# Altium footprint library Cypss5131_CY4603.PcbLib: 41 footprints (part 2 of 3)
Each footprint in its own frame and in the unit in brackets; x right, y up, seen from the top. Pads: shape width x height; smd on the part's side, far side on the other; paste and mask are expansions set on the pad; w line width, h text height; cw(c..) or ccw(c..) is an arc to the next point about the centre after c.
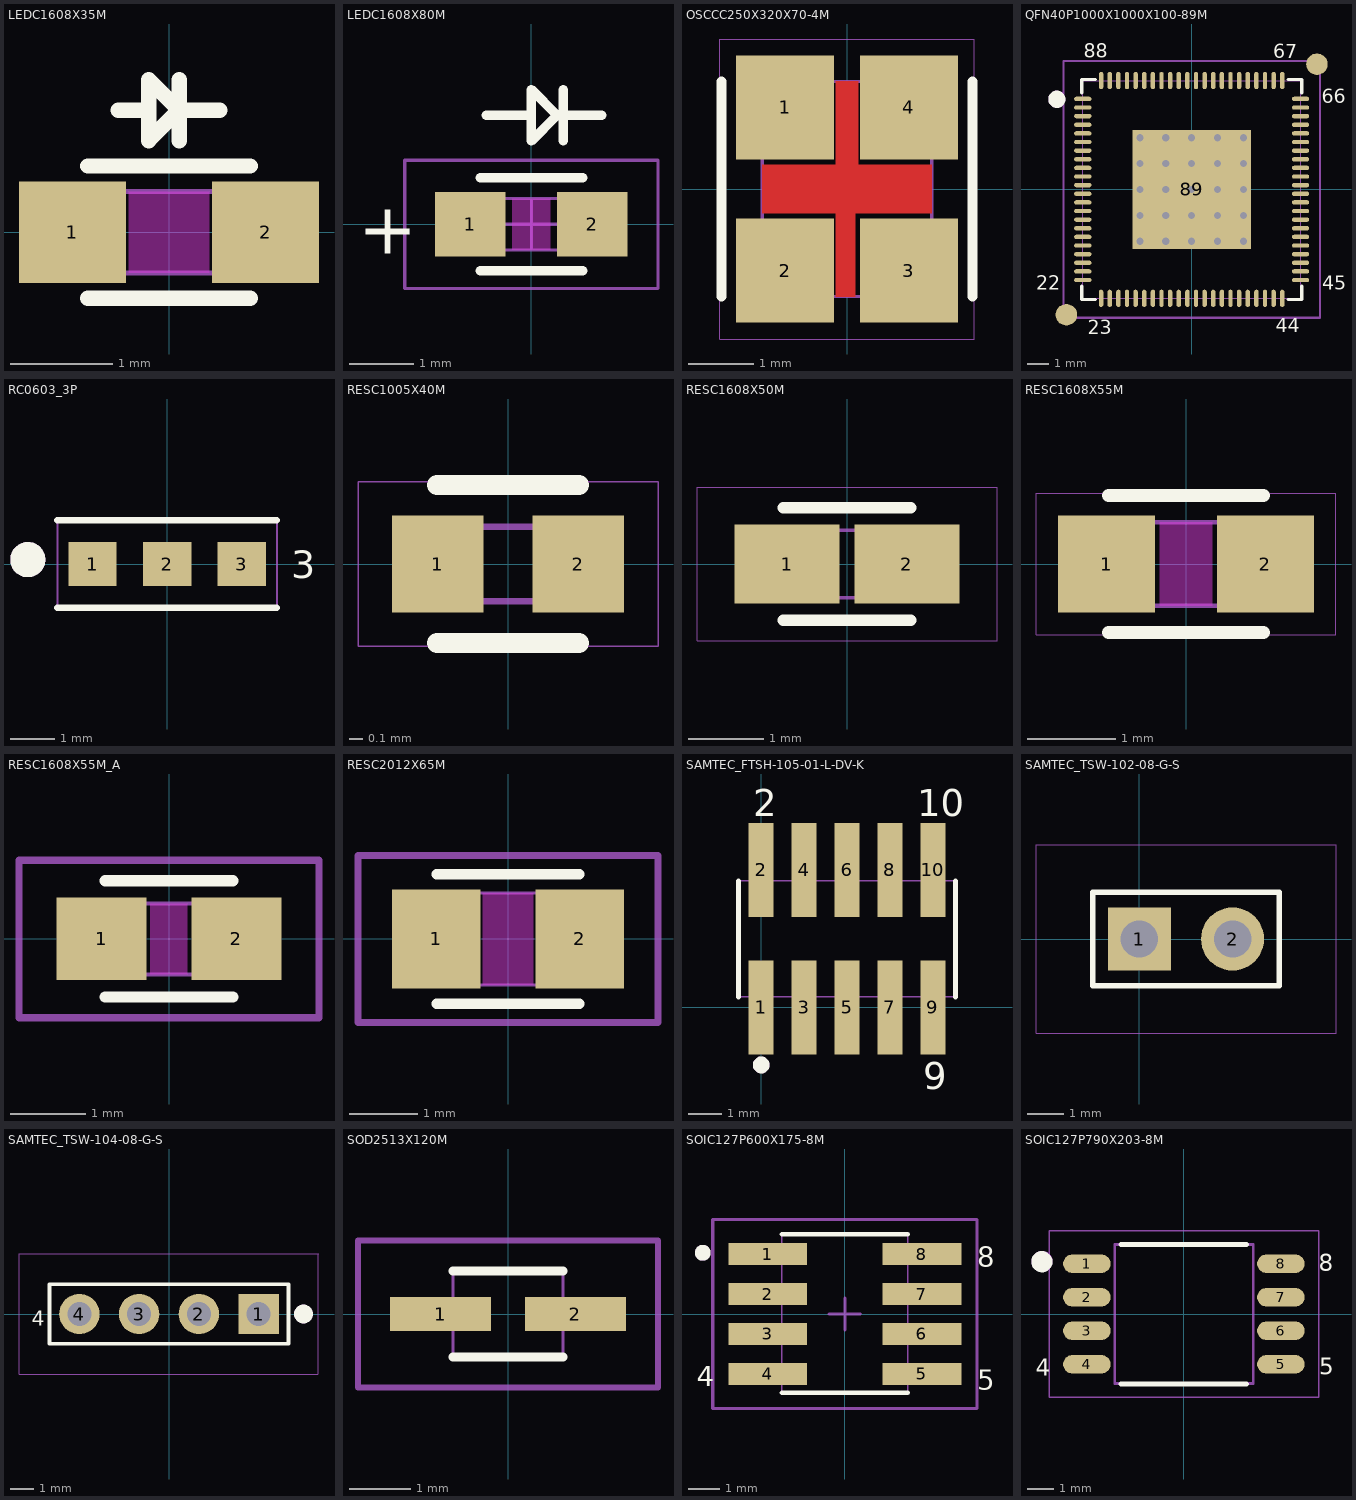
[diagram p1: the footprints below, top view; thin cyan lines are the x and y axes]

## LEDC1608X35M [mm]
height 0.35
pads (2):
  rect 1.05x1 smd mask+0: 1(-0.95,0) 2(0.95,0)
Top Layer keep-out:
  rectangle: -0.4,-0.4 0.4,0.4
Top Overlay:
  lines w0.15: -0.8,-0.65 0.8,-0.65 ; -0.8,0.65 0.8,0.65 ; -0.5,1.2 -0.2,1.2 ; 0.1,0.9 0.1,1.5 ; 0.5,1.2 0.1,1.2 ; 0.1,1.2 -0.2,0.9 -0.2,1.5 0.1,1.2
Mechanical 13:
  lines w0.05: -0.5,1.2 -0.2,1.2 ; 0.1,0.9 0.1,1.5 ; 0.5,1.2 0.1,1.2 ; 0.55,-0.4 0.55,0.4 ; 0.1,1.2 -0.2,0.9 -0.2,1.5 0.1,1.2 ; -0.8,-0.4 -0.8,0.4 0.8,0.4 0.8,-0.4 -0.8,-0.4
Mechanical 14:
  text "R105_100" at -2.4,-1.8 h0.64
  text "LEDC1608X35M" at -3.5,1.9 h0.64
3D body: height 0.35, standoff 0, extent -0.799,-0.4 0.8,0.4

## LEDC1608X80M [mm]
height 0.8
pads (2):
  rect 1.1x1 smd mask+0: 1(-0.95,0) 2(0.95,0)
Top Layer keep-out:
  rectangle: -0.3,-0.4 0.3,0.4
Top Overlay:
  lines w0.15: -0.8,-0.725 0.8,-0.725 ; -0.8,0.725 0.8,0.725 ; -0.7,1.7 0,1.7 ; 0.5,1.3 0.5,2.1 ; 1.1,1.7 0.4,1.7 ; 0,2.1 0,2.1 ; 0,2.1 0.4,1.7 ; 0,2.1 0,1.3 0.4,1.7
  text "+" at -2.705,-0.463 h0.8
  text ".Designator" at -3.7,3.9 h0.8
Mechanical 13:
  lines w0.05: -0.8,-0.4 0.8,-0.4 0.8,0.4 -0.8,0.4 -0.8,-0.4
  text "+" at -2.705,-0.463 h0.8
  text ".Designator" at -4.003,-0.148 h0.8
Mechanical 14:
  text "LEDC1608X80M" at -4.572,2.655 h0.8
  text "R110_100" at -2.851,-2.936 h0.8
Mechanical 15:
  lines w0.05: -0.4,0 0.4,0 ; 0,-0.4 0,0.4 ; -1.975,-1 1.975,-1 1.975,1 -1.975,1 -1.975,-1
3D body: height 0.8, standoff 0, extent -0.8,-0.4 0.8,0.4

## OSCCC250X320X70-4M [mm]
height 0.7
pads (4):
  rect 1.5x1.6 smd mask+0: 1(-0.95,1.25) 2(-0.95,-1.25) 3(0.95,-1.25) 4(0.95,1.25)
Top Layer:
  region: 0.175,1.65 0.175,0.375 1.3,0.375 1.3,-0.375 0.125,-0.375 0.125,-1.65 -0.175,-1.65 -0.175,-0.375 -1.3,-0.375 -1.3,0.375 -0.175,0.375 -0.175,1.65
Top Overlay:
  lines w0.15: -1.925,-1.65 -1.925,1.65 ; 1.925,-1.65 1.925,1.65
  text ".Designator" at -4.085,2.756 h0.8
Mechanical 13:
  lines w0.05: -1.3,-1.65 -1.3,1.65 1.3,1.65 1.3,-1.65 -1.3,-1.65
  text ".Designator" at -3.956,-0.152 h0.8
Mechanical 14:
  text "OSCCC250X320X70-4M" at -6.265,4.123 h0.8
  text "R150_160" at -3.016,-3.593 h0.8
Mechanical 15:
  lines w0.01: -1.95,-2.3 -1.95,2.3 1.95,2.3 1.95,-2.3 -1.95,-2.3
3D body: height 0.7, standoff 0, extent -1.325,-1.675 1.325,1.675

## QFN40P1000X1000X100-89M [mm] "QFN, 88-Leads, Body 10.1x10.1mm (max), Pitch 0.40mm, IPC Low Density"
height 1
pads (91):
  oval 0.8x0.2 smd mask+0: 1(-5.05,4.2) 2(-5.05,3.8) 3(-5.05,3.4) 4(-5.05,3) 5(-5.05,2.6) 6(-5.05,2.2) 7(-5.05,1.8) 8(-5.05,1.4) 9(-5.05,1) 10(-5.05,0.6) 11(-5.05,0.2) 12(-5.05,-0.2) 13(-5.05,-0.6) 14(-5.05,-1) 15(-5.05,-1.4) 16(-5.05,-1.8) 17(-5.05,-2.2) 18(-5.05,-2.6) 19(-5.05,-3) 20(-5.05,-3.4) 21(-5.05,-3.8) 22(-5.05,-4.2) 45(5.05,-4.2) 46(5.05,-3.8) 47(5.05,-3.4) 48(5.05,-3) 49(5.05,-2.6) 50(5.05,-2.2) 51(5.05,-1.8) 52(5.05,-1.4) 53(5.05,-1) 54(5.05,-0.6) 55(5.05,-0.2) 56(5.05,0.2) 57(5.05,0.6) 58(5.05,1) 59(5.05,1.4) 60(5.05,1.8) 61(5.05,2.2) 62(5.05,2.6) 63(5.05,3) 64(5.05,3.4) 65(5.05,3.8) 66(5.05,4.2)
  oval 0.2x0.8 smd mask+0: 23(-4.2,-5.05) 24(-3.8,-5.05) 25(-3.4,-5.05) 26(-3,-5.05) 27(-2.6,-5.05) 28(-2.2,-5.05) 29(-1.8,-5.05) 30(-1.4,-5.05) 31(-1,-5.05) 32(-0.6,-5.05) 33(-0.2,-5.05) 34(0.2,-5.05) 35(0.6,-5.05) 36(1,-5.05) 37(1.4,-5.05) 38(1.8,-5.05) 39(2.2,-5.05) 40(2.6,-5.05) 41(3,-5.05) 42(3.4,-5.05) 43(3.8,-5.05) 44(4.2,-5.05) 67(4.2,5.05) 68(3.8,5.05) 69(3.4,5.05) 70(3,5.05) 71(2.6,5.05) 72(2.2,5.05) 73(1.8,5.05) 74(1.4,5.05) 75(1,5.05) 76(0.6,5.05) 77(0.2,5.05) 78(-0.2,5.05) 79(-0.6,5.05) 80(-1,5.05) 81(-1.4,5.05) 82(-1.8,5.05) 83(-2.2,5.05) 84(-2.6,5.05) 85(-3,5.05) 86(-3.4,5.05) 87(-3.8,5.05) 88(-4.2,5.05)
  rect 5.5x5.5 smd mask+0: 89(0,0)
  round 1 smd mask+0.5: ""(-5.81,-5.81) ""(5.81,5.81)
via 2.4,-2.4 diameter 0.66 hole 0.33
via 1.2,-2.4 diameter 0.66 hole 0.33
via 0,-2.4 diameter 0.66 hole 0.33
via -1.2,-2.4 diameter 0.66 hole 0.33
via -2.4,-2.4 diameter 0.66 hole 0.33
via 2.4,-1.2 diameter 0.66 hole 0.33
via 1.2,-1.2 diameter 0.66 hole 0.33
via 0,-1.2 diameter 0.66 hole 0.33
via -1.2,-1.2 diameter 0.66 hole 0.33
via -2.4,-1.2 diameter 0.66 hole 0.33
via 2.4,0 diameter 0.66 hole 0.33
via 1.2,0 diameter 0.66 hole 0.33
via 0,0 diameter 0.66 hole 0.33
via -1.2,0 diameter 0.66 hole 0.33
via -2.4,0 diameter 0.66 hole 0.33
via 2.4,1.2 diameter 0.66 hole 0.33
via 1.2,1.2 diameter 0.66 hole 0.33
via 0,1.2 diameter 0.66 hole 0.33
via -1.2,1.2 diameter 0.66 hole 0.33
via -2.4,1.2 diameter 0.66 hole 0.33
via 2.4,2.4 diameter 0.66 hole 0.33
via 1.2,2.4 diameter 0.66 hole 0.33
via 0,2.4 diameter 0.66 hole 0.33
via -1.2,2.4 diameter 0.66 hole 0.33
via -2.4,2.4 diameter 0.66 hole 0.33
Top Overlay:
  circle w0.4: c-6.252,4.181 r0.2
  lines w0.15: -5.1,-4.475 -5.1,-5.1 -4.475,-5.1 ; -5.1,4.475 -5.1,5.1 -4.475,5.1 ; 4.475,-5.1 5.1,-5.1 5.1,-4.475 ; 4.475,5.1 5.1,5.1 5.1,4.475
  text "88" at -5.003,6.115 h0.64
  text "67" at 3.775,6.092 h0.64
  text "66" at 6.042,4.005 h0.64
  text "45" at 6.058,-4.646 h0.64
  text "44" at 3.892,-6.619 h0.64
  text "23" at -4.819,-6.707 h0.64
  text "22" at -7.22,-4.66 h0.64
  text ".Designator" at -3.931,7.075 h0.8
Mechanical 13:
  circle w0.4: c-6.252,4.187 r0.2
  lines w0.05: -5.05,-5.05 5.05,-5.05 5.05,5.05 -5.05,5.05 -5.05,-5.05
  text ".Designator" at -4.14,-0.317 h0.8
Mechanical 14:
  text "QFN40P1000X1000X100-89M" at -8.348,8.365 h0.8
  text "B80_20" at -2.081,-8.548 h0.8
Mechanical 15:
  lines w0.1: -0.5,0 0.5,0 ; 0,-0.5 0,0.5 ; -5.95,-5.95 5.95,-5.95 5.95,5.95 -5.95,5.95 -5.95,-5.95
3D body: height 1, standoff 0.05, extent -5.05,-5.05 5.05,5.05

## RC0603_3P [mm]
height 2.388
pads (3):
  rect 1.1x1 smd mask+0.079: 1(-1.7,0) 2(0,0) 3(1.7,0)
Top Overlay:
  circle w0.4: c-3.175,0.1 r0.2
  lines w0.15: -2.5,-1 2.5,-1 ; -2.5,1 2.5,1
  text ".Designator" at -2.5,2 h0.64
  text "3" at 2.825,-0.325 h0.64
Mechanical 13:
  circle w0.4: c-3.175,0.1 r0.2
  lines w0.05: -2.5,-1 -2.5,1 2.5,1 2.5,-1 -2.5,-1
  text ".Designator" at -2.5,0 h0.64
Mechanical 14:
  text "RC0603_3P" at -2.5,3 h0.64
3D body: height 0, standoff 0, extent -2.499,-0.999 2.499,0.999

## RESC1005X40M [mm]
height 0.4
pads (2):
  rect 0.68x0.72 smd mask+0: 1(-0.52,0) 2(0.52,0)
Top Overlay:
  lines w0.15: -0.525,-0.585 0.525,-0.585 ; -0.525,0.585 0.525,0.585
  text ".Designator" at -4.117,1.111 h0.8
Mechanical 13:
  lines w0.05: -0.525,-0.275 -0.525,0.275 0.525,0.275 0.525,-0.275 -0.525,-0.275
  text ".Designator" at -3.929,-2.074 h0.8
Mechanical 14:
  text "RESC1005X40M" at -4.558,2.35 h0.8
  text "R68_72" at -2.332,-1.954 h0.8
Mechanical 15:
  lines w0.01: -1.11,-0.61 -1.11,0.61 1.11,0.61 1.11,-0.61 -1.11,-0.61
3D body: height 0.4, standoff 0, extent -0.55,-0.3 0.55,0.3

## RESC1608X50M [mm] "Chip Resistor, 2-Leads, Body 1.5x0.8mm, IPC Low Density"
height 0.5
pads (2):
  rect 1.4x1.05 smd mask+0: 1(-0.8,0) 2(0.8,0)
Top Overlay:
  lines w0.15: -0.85,-0.75 0.85,-0.75 ; -0.85,0.75 0.85,0.75
  text ".Designator" at -3.98,1.71 h0.8
Mechanical 13:
  lines w0.05: -0.85,-0.45 0.85,-0.45 0.85,0.45 -0.85,0.45 -0.85,-0.45
  text ".Designator" at -4.146,-0.319 h0.8
Mechanical 14:
  text "RESC1608X50M" at -4.13,2.972 h0.8
  text "R105_140" at -2.942,-2.822 h0.8
Mechanical 15:
  lines w0.01: -2,-1.025 2,-1.025 2,1.025 -2,1.025 -2,-1.025
3D body: height 0.5, standoff 0, extent -0.85,-0.45 0.85,0.45

## RESC1608X55M [mm]
height 0.55
pads (2):
  rect 1.1x1.1 smd mask+0: 1(-0.9,0) 2(0.9,0)
Top Layer keep-out:
  rectangle: -0.3,-0.475 0.3,0.475
Top Overlay:
  lines w0.15: -0.875,-0.775 0.875,-0.775 ; -0.875,0.775 0.875,0.775
  text ".Designator" at -3.93,1.311 h0.8
Mechanical 13:
  lines w0.05: -0.875,-0.475 -0.875,0.475 0.875,0.475 0.875,-0.475 -0.875,-0.475
  text ".Designator" at -4.025,-0.209 h0.8
Mechanical 14:
  text "RESC1608X55M" at -4.531,2.562 h0.8
  text "S110" at -1.175,-1.998 h0.8
Mechanical 15:
  lines w0.01: -1.7,-0.8 -1.7,0.8 1.7,0.8 1.7,-0.8 -1.7,-0.8
3D body: height 0.55, standoff 0, extent -0.874,-0.474 0.874,0.474

## RESC1608X55M_A [mm]
height 0.55
pads (2):
  rect 1.2x1.1 smd mask+0: 1(-0.9,0) 2(0.9,0)
Top Layer keep-out:
  rectangle: -0.25,-0.475 0.25,0.475
Top Overlay:
  lines w0.15: -0.85,-0.775 0.85,-0.775 ; -0.85,0.775 0.85,0.775
  text ".Designator" at -4.086,1.532 h0.8
Mechanical 13:
  lines w0.05: -0.85,-0.475 0.85,-0.475 0.85,0.475 -0.85,0.475 -0.85,-0.475
  text ".Designator" at -4.122,-0.16 h0.8
Mechanical 14:
  text "R120_110" at -2.781,-2.431 h0.8
  text "RESC1608X55M_A" at -5.021,2.642 h0.8
Mechanical 15:
  lines w0.1: -2,-1.05 2,-1.05 2,1.05 -2,1.05 -2,-1.05
3D body: height 0.55, standoff 0, extent -0.85,-0.475 0.85,0.475

## RESC2012X65M [mm]
height 0.65
pads (2):
  rect 1.3x1.45 smd mask+0: 1(-1.05,0) 2(1.05,0)
Top Layer keep-out:
  rectangle: -0.375,-0.675 0.375,0.675
Top Overlay:
  lines w0.15: -1.05,-0.95 1.05,-0.95 ; -1.05,0.95 1.05,0.95
  text ".Designator" at -3.982,1.817 h0.8
Mechanical 13:
  lines w0.05: -1.05,-0.675 -1.05,0.675 1.05,0.675 1.05,-0.675 -1.05,-0.675
  text ".Designator" at -4.056,-0.095 h0.8
Mechanical 14:
  text "RESC2012X65M" at -4.8,2.975 h0.8
  text "R145_130" at -2.925,-2.5 h0.8
Mechanical 15:
  lines w0.1: -2.2,-1.225 -2.2,1.225 2.2,1.225 2.2,-1.225 -2.2,-1.225
3D body: height 0.65, standoff 0, extent -1.05,-0.675 1.05,0.675

## SAMTEC_FTSH-105-01-L-DV-K [mm]
height 5.715
pads (10):
  rect 0.74x2.79 smd mask+0: 1(0,0) 2(0,4.07) 3(1.27,0) 4(1.27,4.07) 5(2.54,0) 6(2.54,4.07) 7(3.81,0) 8(3.81,4.07) 9(5.08,0) 10(5.08,4.07)
Top Overlay:
  circle w0.25: c0.002,-1.702 r0.125
  lines w0.152: -0.673,0.318 -0.673,3.746 ; 5.753,0.318 5.753,3.746
  text ".Designator" at -1.346,6.782 h0.8
  text "2" at -0.229,5.664 h0.8
  text "9" at 4.801,-2.413 h0.8
  text "10" at 4.623,5.664 h0.8
Mechanical 13:
  circle w0.25: c0.002,-1.702 r0.125
  lines w0.051: -0.673,0.318 5.753,0.318 5.753,3.746 -0.673,3.746 -0.673,0.318
  text ".Designator" at -1.595,1.916 h0.8
Mechanical 14:
  text "R74_279" at -0.178,-3.531 h0.8
  text "SAMTEC_FTSH-105-01-L-DV-K" at -6.401,8.077 h0.8
3D body: height 5.71, standoff 0, extent -0.673,0.318 5.753,3.746

## SAMTEC_TSW-102-08-G-S [mm]
height 8.382
pads (2):
  rect 1.72x1.72 / inner round 1.72 / far side rect 1.72x1.72 hole 1.02 mask+0: 1(0,0)
  round 1.72 hole 1.02 mask+0: 2(2.54,0)
Top Overlay:
  lines w0.152: -1.27,-1.27 -1.27,1.27 3.81,1.27 3.81,-1.27 -1.27,-1.27
  text ".Designator" at -2.624,2.948 h0.8
Mechanical 13:
  lines w0.051: -1.27,-1.27 -1.27,1.27 3.81,1.27 3.81,-1.27 -1.27,-1.27
  text ".Designator" at -2.967,-0.239 h0.8
Mechanical 14:
  text "S172H102" at -1.161,-4.911 h0.8
  text "C172H102" at -1.159,-3.674 h0.8
  text "SAMTEC_TSW-102-08-G-S" at -5.909,4.204 h0.8
Mechanical 15:
  lines w0.025: -2.819,-2.565 5.359,-2.565 5.359,2.565 -2.819,2.565 -2.819,-2.565
3D body: height 8.38, standoff 0, extent -1.295,-1.295 3.835,1.295

## SAMTEC_TSW-104-08-G-S [mm]
height 8.38
pads (4):
  rect 1.72x1.72 hole 1.02 mask+0: 1(3.81,0)
  round 1.72 hole 1.02 mask+0: 2(1.27,0) 3(-1.27,0) 4(-3.81,0)
Top Overlay:
  circle w0.4: c5.715,0 r0.2
  lines w0.152: -5.08,-1.27 -5.08,1.27 5.08,1.27 5.08,-1.27 -5.08,-1.27
  text "4" at -5.842,-0.508 h0.64
  text ".Designator" at -3.048,1.651 h0.64
Mechanical 13:
  circle w0.4: c5.715,0 r0.2
  lines w0.051: -5.08,-1.27 5.08,-1.27 5.08,1.27 -5.08,1.27 -5.08,-1.27
  text ".Designator" at -3.048,-0.381 h0.64
Mechanical 14:
  text "SAMTEC_TSW-104-08-G-S" at -6.985,2.921 h0.64
Mechanical 15:
  lines w0.051: -6.375,-2.565 -6.375,2.565 6.375,2.565 6.35,2.54 6.35,-2.54 6.325,-2.565 -6.375,-2.565
Mechanical 20:
  text "SAMTEC_TSW-104-08-G-S" at -6.745,4.239 h0.64
  text "S172H102" at -2.286,-5.334 h0.64
  text "C172H102" at -2.286,-4.064 h0.64
3D body: height 8.38, standoff 0, extent -5.105,-1.295 5.105,1.295

## SOD2513X120M [mm] "SOIC, 2-Leads, Body 1.4x1.8mm (max), Pitch 1.27mm, IPC Low Density"
height 1.2
pads (2):
  rect 1.65x0.55 smd mask+0: 1(-1.1,0) 2(1.1,0)
Top Overlay:
  lines w0.15: -0.9,-0.7 0.9,-0.7 ; -0.9,0.7 0.9,0.7
  text ".Designator" at -3.1,1.6 h0.64
Mechanical 13:
  lines w0.05: -0.9,-0.7 0.9,-0.7 0.9,0.7 -0.9,0.7 -0.9,-0.7
  text ".Designator" at -3.1,-0.2 h0.64
Mechanical 14:
  text "SOD2513X120M" at -3.6,3 h0.64
Mechanical 15:
  lines w0.1: -2.45,-1.2 2.45,-1.2 2.45,1.2 -2.45,1.2 -2.45,-1.2
3D body: height 1.2, standoff 0.1, extent -0.9,-0.7 0.9,0.7

## SOIC127P600X175-8M [mm] "SOIC, 8-Leads, Body 5.0x4.0mm (max), Pitch 1.27mm, IPC Low Density"
height 1.75
pads (8):
  rect 2.5x0.7 smd mask+0: 1(-2.45,1.905) 2(-2.45,0.635) 3(-2.45,-0.635) 4(-2.45,-1.905) 5(2.45,-1.905) 6(2.45,-0.635) 7(2.45,0.635) 8(2.45,1.905)
Top Overlay:
  circle w0.25: c-4.516,1.945 r0.125
  lines w0.15: -2,-2.5 2,-2.5 ; -2,2.532 2,2.532
  text "8" at 4.2,1.5 h0.64
  text "5" at 4.2,-2.4 h0.64
  text "4" at -4.7,-2.3 h0.64
  text ".Designator" at -3.865,3.628 h0.8
Mechanical 13:
  circle w0.25: c-4.516,1.946 r0.125
  lines w0.05: -2,-2.5 -2,2.5 2,2.5 2,-2.5 -2,-2.5
  text ".Designator" at -3.7,-0.2 h0.8
Mechanical 14:
  text "R250_70" at -2.893,-4.166 h0.8
  text "SOIC127P600X175-8M" at -6.556,4.864 h0.8
Mechanical 15:
  lines w0.1: -0.5,0 0.5,0 ; 0,-0.5 0,0.5 ; -4.2,-3 -4.2,3 4.2,3 4.2,-3 -4.2,-3
3D body: height 1.75, standoff 0.1, extent -2,-2.5 2,2.5

## SOIC127P790X203-8M [mm] "SOIC, 8-Leads, Body 5.3x5.3mm (max), Pitch 1.27mm, IPC Low Density"
height 2.03
pads (8):
  oval 1.8x0.7 smd mask+0: 1(-3.675,1.905) 2(-3.675,0.635) 3(-3.675,-0.635) 4(-3.675,-1.905) 5(3.675,-1.905) 6(3.675,-0.635) 7(3.675,0.635) 8(3.675,1.905)
Top Overlay:
  circle w0.4: c-5.38,1.981 r0.2
  lines w0.2: -2.375,-2.65 2.375,-2.65 ; -2.375,2.63 2.375,2.63
  text ".Designator" at -3.277,3.683 h0.64
  text "4" at -5.601,-2.337 h0.64
  text "5" at 5.126,-2.305 h0.64
  text "8" at 5.111,1.628 h0.64
Mechanical 13:
  circle w0.4: c-5.373,1.988 r0.2
  lines w0.1: -2.625,-2.63 -2.625,2.63 2.625,2.63 2.625,-2.63 -2.625,-2.63
  text ".Designator" at -2.886,-0.261 h0.64
Mechanical 14:
  text "SOIC127P790X203-8M" at -5.08,4.953 h0.64
  text "B70_180" at -2.445,-4.893 h0.64
Mechanical 15:
  lines w0.05: -5.1,-3.15 -5.1,3.15 5.1,3.15 5.1,-3.15 -5.1,-3.15
3D body: height 2.03, standoff 0.15, extent -2.625,-2.63 2.625,2.63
